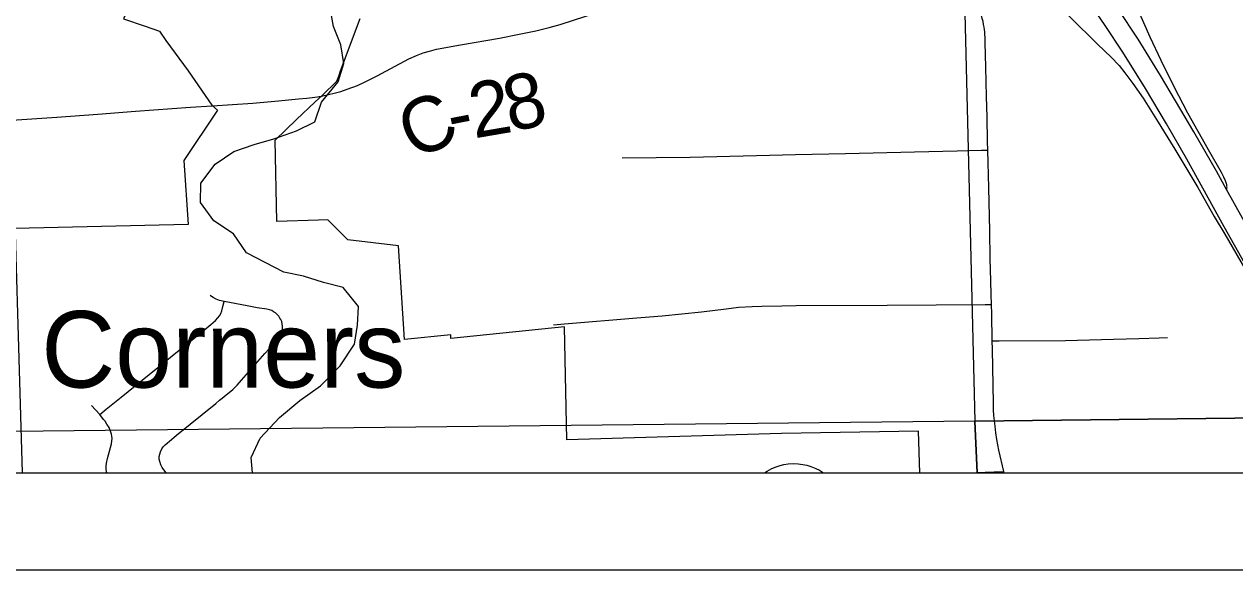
# Model space of a CAD drawing. Extents: x -6.4 to 34, y -4.2 to 22.
# Drawn here: x 7.115 to 8.363, y 14 to 14.563 of the extents above; entities that cross this region are included whole.
import ezdxf

# ---------------------------------------------------------------- set-up
doc = ezdxf.new("R2010")
doc.units = 0
for name, color, linetype in [('GM_X_City_Street', 7, 'Continuous'), ('GM_X_Corporation', 7, 'Continuous'), ('GM_X_County_Road', 7, 'Continuous'), ('GM_X_County_Road_Text', 7, 'Continuous'), ('GM_X_Interchange_Ramps', 7, 'Continuous'), ('GM_X_Minor_River', 7, 'Continuous'), ('GM_X_State_Route', 7, 'Continuous'), ('GM_X_Township_Road', 7, 'Continuous'), ('GM_X_Unincorporated_Text', 7, 'Continuous'), ('SH_Data', 7, 'Continuous')]:
    doc.layers.add(name, color=color, linetype=linetype)

msp = doc.modelspace()

# ---------------------------------------------------------------- linework, layer by layer
at = {"layer": 'GM_X_City_Street'}
for points in [[(7.1925, 14.1603), (7.199, 14.1657), (7.2144, 14.1782), (7.2434, 14.2017), (7.254, 14.2102), (7.2709, 14.2239), (7.2945, 14.243), (7.3071, 14.2532), (7.3118, 14.2573), (7.3144, 14.26), (7.316, 14.2621), (7.3172, 14.2644), (7.3183, 14.2674), (7.3194, 14.2717), (7.3208, 14.2769)], [(7.2609, 14.1), (7.2586, 14.103), (7.2567, 14.1056), (7.2553, 14.1085), (7.2543, 14.1116), (7.2539, 14.1142), (7.2539, 14.1168), (7.2543, 14.1194), (7.2551, 14.1219), (7.2565, 14.1249), (7.258, 14.127), (7.2598, 14.1289), (7.2665, 14.1346), (7.2718, 14.1389), (7.3122, 14.1718), (7.3159, 14.175), (7.3189, 14.1773), (7.3227, 14.1805), (7.3261, 14.183), (7.3298, 14.1862), (7.3341, 14.1906), (7.3387, 14.1956), (7.3628, 14.2231), (7.3716, 14.2328), (7.376, 14.2379), (7.3781, 14.2408), (7.3797, 14.244), (7.3807, 14.2468), (7.3811, 14.2491), (7.3811, 14.2515), (7.3808, 14.2538), (7.3802, 14.2561), (7.3792, 14.2582), (7.3783, 14.2597), (7.3771, 14.2617), (7.3755, 14.2636), (7.3738, 14.2651), (7.3718, 14.2664), (7.3699, 14.2675), (7.3676, 14.2682), (7.3648, 14.2689), (7.355, 14.2705), (7.3446, 14.2724), (7.3208, 14.2769), (7.316, 14.2781), (7.3124, 14.2794), (7.3095, 14.2809), (7.3079, 14.282), (7.3062, 14.2831)], [(7.1997, 14.1), (7.1994, 14.1011), (7.1991, 14.1041), (7.1991, 14.1071), (7.1994, 14.1101), (7.2005, 14.1148), (7.2037, 14.1262), (7.2047, 14.1299), (7.205, 14.1331), (7.2052, 14.1355), (7.205, 14.1378), (7.2044, 14.1401), (7.2035, 14.1432), (7.202, 14.1468), (7.1999, 14.1504), (7.1979, 14.1533), (7.1964, 14.1552), (7.1925, 14.1603), (7.1838, 14.1695)], [(7.8783, 14.1), (7.881, 14.1018), (7.8858, 14.1044), (7.8903, 14.1064), (7.8943, 14.1078), (7.8984, 14.1088), (7.9027, 14.1093), (7.9082, 14.1096), (7.913, 14.1094), (7.9179, 14.1088), (7.922, 14.1079), (7.9261, 14.1066), (7.9313, 14.1046), (7.9351, 14.1027), (7.9381, 14.1007), (7.9391, 14.1)]]:
    msp.add_lwpolyline(points, dxfattribs=at)
at = {"layer": 'GM_X_Corporation'}
for points in [[(7.1124, 14.1), (8.9, 14.1), (8.9, 15.9356), (8.6815, 15.9311), (7.2926, 15.9044), (7.2702, 15.904), (7.0636, 15.9014), (7.0744, 15.3393), (7.0897, 14.8536), (7.0948, 14.7153), (7.0983, 14.5939), (7.1017, 14.4646)], [(7.0784, 15.1559), (8.0705, 15.1646), (8.0954, 14.1535), (7.1021, 14.1428), (7.0887, 14.7028)], [(8.9, 14.1628), (8.9, 15.1746), (8.0705, 15.1646), (8.0954, 14.1535)], [(7.1031, 14.1), (8.0976, 14.1), (8.0954, 14.1535), (7.1021, 14.1428)], [(8.0976, 14.1), (8.9, 14.1), (8.9, 14.1628), (8.0954, 14.1535)]]:
    msp.add_lwpolyline(points, close=True, dxfattribs=at)
for points in [[(7.1027, 14.8733), (7.1366, 14.8546), (7.1919, 14.8297), (7.2343, 14.8108), (7.2408, 14.6721), (7.2408, 14.6174), (7.2169, 14.5686), (7.2392, 14.5612), (7.254, 14.5558), (7.2606, 14.5463), (7.2838, 14.5151), (7.3082, 14.4794), (7.314, 14.4744), (7.2792, 14.4225), (7.2836, 14.3565), (7.1047, 14.3522)], [(6.8155, 14.1), (8.0384, 14.1), (8.0373, 14.1431), (7.8957, 14.1406), (7.6742, 14.1341), (7.6719, 14.2506), (7.5547, 14.2388), (7.5546, 14.2425), (7.5067, 14.2377), (7.5005, 14.3342), (7.4483, 14.3405), (7.4277, 14.3612), (7.418, 14.3609), (7.3753, 14.3595), (7.3735, 14.4435), (7.3956, 14.4649), (7.4145, 14.4827), (7.4223, 14.4898), (7.4372, 14.5043), (7.439, 14.5096), (7.441, 14.515), (7.4612, 14.5691)]]:
    msp.add_lwpolyline(points, dxfattribs=at)
at = {"layer": 'GM_X_County_Road'}
for points in [[(8.1057, 14.5519), (8.1057, 14.5528), (8.1055, 14.5551), (8.1052, 14.5574), (8.1048, 14.5601), (8.1043, 14.5628), (8.1038, 14.5659), (8.1029, 14.569), (8.102, 14.5722), (8.1008, 14.5757), (8.0996, 14.5791), (8.0982, 14.5828), (8.0964, 14.5868), (8.093, 14.594), (8.0863, 14.6073), (8.0805, 14.6183), (8.0739, 14.6317), (8.0706, 14.6387), (8.0675, 14.6452)], [(7.4225, 14.4892), (7.4344, 14.4919), (7.4412, 14.4938), (7.4478, 14.4959), (7.4582, 14.5), (7.4662, 14.5035), (7.4785, 14.5097), (7.5113, 14.5272), (7.5192, 14.5307), (7.5261, 14.5334), (7.5326, 14.5354), (7.5398, 14.5372), (7.5646, 14.5419), (7.6049, 14.5488), (7.6251, 14.5527), (7.6422, 14.5563), (7.6561, 14.5597), (7.6674, 14.5629), (7.6941, 14.5715), (7.7382, 14.5843), (7.7527, 14.5877), (7.8166, 14.6008), (7.8947, 14.6157), (7.9664, 14.6288)], [(8.1254, 14.1), (8.1251, 14.1014), (8.1201, 14.1234), (8.119, 14.1288), (8.118, 14.1344), (8.1169, 14.1413), (8.1161, 14.1482), (8.1155, 14.1538), (8.115, 14.1594), (8.1147, 14.1652), (8.1144, 14.1715), (8.1134, 14.2276), (8.1132, 14.2362), (8.1127, 14.2642), (8.1124, 14.2739), (8.1121, 14.2841), (8.1118, 14.2984), (8.1112, 14.3208), (8.1106, 14.3499), (8.1096, 14.3941), (8.109, 14.4202), (8.1087, 14.4332), (8.1085, 14.4419), (8.1079, 14.4673), (8.1074, 14.4884), (8.1067, 14.5186), (8.1061, 14.5443), (8.1058, 14.5501), (8.1057, 14.5519)], [(7.3084, 14.4789), (7.3504, 14.4817), (7.377, 14.4839), (7.3974, 14.4859), (7.406, 14.4867), (7.417, 14.4882), (7.4225, 14.4892)], [(7.1019, 14.4641), (7.1483, 14.4673), (7.1904, 14.4704), (7.2293, 14.4735), (7.2862, 14.4774), (7.3084, 14.4789)]]:
    msp.add_lwpolyline(points, dxfattribs=at)
at = {"layer": 'GM_X_Interchange_Ramps'}
for points in [[(8.3549, 14.3926), (8.3553, 14.3936), (8.3554, 14.3944), (8.3555, 14.3952), (8.3554, 14.3959), (8.3553, 14.3967), (8.3552, 14.3976), (8.355, 14.3983), (8.3547, 14.3994), (8.3543, 14.4003), (8.354, 14.4013), (8.3522, 14.4053), (8.3498, 14.41), (8.3362, 14.4333), (8.315, 14.4713), (8.3009, 14.4983), (8.2874, 14.5256), (8.2761, 14.5498), (8.2631, 14.5794), (8.251, 14.608), (8.2411, 14.633), (8.2368, 14.6453), (8.2327, 14.656)], [(8.1249, 14.6484), (8.1273, 14.6433), (8.1301, 14.6381), (8.1333, 14.632), (8.1363, 14.6274), (8.141, 14.6216), (8.1497, 14.6127), (8.194, 14.57), (8.222, 14.5426), (8.2358, 14.5291), (8.2441, 14.5203), (8.2502, 14.5129), (8.2583, 14.5018), (8.2689, 14.4866), (8.2828, 14.4649), (8.3016, 14.4342), (8.3253, 14.3945), (8.3423, 14.3647), (8.3533, 14.3463), (8.3773, 14.3047)]]:
    msp.add_lwpolyline(points, dxfattribs=at)
at = {"layer": 'GM_X_Minor_River'}
msp.add_lwpolyline([(7.3501, 14.1), (7.3486, 14.116), (7.3578, 14.1357), (7.378, 14.1573), (7.3989, 14.1746), (7.4202, 14.1897), (7.4404, 14.2105), (7.4553, 14.2329), (7.4585, 14.2526), (7.4594, 14.2716), (7.4436, 14.2914), (7.4232, 14.2964), (7.4028, 14.303), (7.3823, 14.3073), (7.3438, 14.3272), (7.3303, 14.3466), (7.3103, 14.36), (7.2965, 14.379), (7.2966, 14.3992), (7.3115, 14.4188), (7.3309, 14.4317), (7.3517, 14.4388), (7.3722, 14.4448), (7.3953, 14.453), (7.4143, 14.4624), (7.4213, 14.4825), (7.4384, 14.5037), (7.4442, 14.5227), (7.4413, 14.5417), (7.4335, 14.5607), (7.4302, 14.5797)], dxfattribs=at)
at = {"layer": 'GM_X_State_Route'}
for points in [[(8.518, 14.1), (8.491, 14.1484), (8.4758, 14.1756), (8.4679, 14.1897), (8.451, 14.2201), (8.3999, 14.3119), (8.3794, 14.3489), (8.3716, 14.363), (8.3549, 14.3926), (8.3447, 14.4114), (8.3212, 14.452), (8.3024, 14.484), (8.2867, 14.5102), (8.2637, 14.5475), (8.2428, 14.5792), (8.2101, 14.6268), (8.2013, 14.6392), (8.1947, 14.6485)], [(8.3875, 14.2918), (8.3526, 14.3541), (8.3141, 14.4237), (8.293, 14.4603), (8.2712, 14.4966), (8.2479, 14.5341), (8.2299, 14.5617), (8.2012, 14.6038)]]:
    msp.add_lwpolyline(points, dxfattribs=at)
at = {"layer": 'GM_X_Township_Road'}
msp.add_line((7.6607, 14.2529), (7.672, 14.254), dxfattribs=at)
for points in [[(7.7314, 14.4251), (7.8016, 14.426), (7.8699, 14.4277), (7.9102, 14.4286), (7.9618, 14.4296), (8.0332, 14.4313), (8.077, 14.4324), (8.1022, 14.433), (8.1087, 14.4332)], [(7.672, 14.254), (7.7466, 14.2599), (7.7726, 14.2621), (7.8134, 14.2663), (7.8389, 14.2695), (7.8515, 14.2709), (7.8657, 14.2719), (7.8756, 14.2722), (7.8961, 14.2726), (7.911, 14.2727), (8.0048, 14.2732), (8.1061, 14.2739), (8.1124, 14.2739)], [(8.1132, 14.2362), (8.1205, 14.2363), (8.1888, 14.2368), (8.2385, 14.2381), (8.2644, 14.2388), (8.2855, 14.2394), (8.2942, 14.2398)], [(8.0877, 14.1), (8.1153, 14.101), (8.1251, 14.1014)]]:
    msp.add_lwpolyline(points, dxfattribs=at)
at = {"layer": 'SH_Data'}
for p, q in [((2.1, 14.1), (8.9, 14.1)), ((2, 14), (9, 14))]:
    msp.add_line(p, q, dxfattribs=at)

# ---------------------------------------------------------------- texts
at = {"layer": 'GM_X_County_Road_Text'}
for s, rotation, p in [('8', 12.2769, (7.6158, 14.4516)), ('2', 9.7335, (7.5786, 14.4451)), ('C', 24.6883, (7.517, 14.4224)), ('-', 11.0038, (7.556, 14.4408))]:
    msp.add_text(s, height=0.0568, rotation=rotation, dxfattribs=at).set_placement(p)
at = {"layer": 'GM_X_Unincorporated_Text'}
msp.add_text('Tibbetts Corners', height=0.078977, rotation=0, dxfattribs=at).set_placement((6.7271, 14.1881))

doc.saveas('drawing.dxf')
